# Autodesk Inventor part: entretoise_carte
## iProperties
Created: 2011-01
Part Number: entretoise_carte
Document SubType Name: Modeling
Designer: eric
Density: 1 g/cm^3
Mass: 0.219826 g
Surface Area: 3.29692 cm^2
Volume: 0.219826 cm^3
Author: eric
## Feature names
1. Base1
